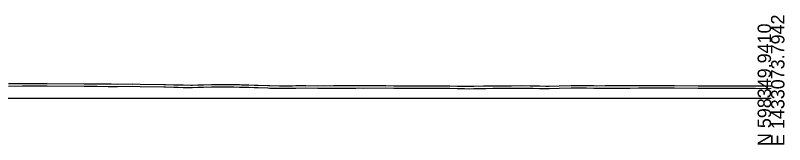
# Model space of a CAD drawing. Extents: x -26 to 2203, y -10 to 12201.
# Drawn here: x 442.1 to 602.8, y 1990.3 to 2017.3 of the extents above; entities that cross this region are included whole.
import ezdxf

# ---------------------------------------------------------------- set-up
doc = ezdxf.new("R2010")
doc.units = 0
for name, color, linetype in [('DESIGN - SHEET - Light Grid', 7, 'Continuous'), ('SURVEY - GROUND - Bottom of Topsoil Layer', 7, 'Continuous'), ('SURVEY - GROUND - Top of Ground', 7, 'Continuous')]:
    doc.layers.add(name, color=color, linetype=linetype)

msp = doc.modelspace()

# ---------------------------------------------------------------- linework, layer by layer
at = {"layer": 'DESIGN - SHEET - Light Grid'}
msp.add_line((300, 2000), (600, 2000), dxfattribs=at)
at = {"layer": 'SURVEY - GROUND - Bottom of Topsoil Layer'}
for p, q in [((440.59, 2002.54), (443.51, 2002.59)), ((443.51, 2002.59), (444.6, 2002.55)), ((444.6, 2002.55), (448.7, 2002.59)), ((448.7, 2002.59), (456.41, 2002.5)), ((456.41, 2002.5), (457.53, 2002.5)), ((457.53, 2002.5), (459.12, 2002.48)), ((459.12, 2002.48), (461.46, 2002.47)), ((461.46, 2002.47), (462.04, 2002.47)), ((462.04, 2002.47), (463.42, 2002.45)), ((463.42, 2002.45), (466.53, 2002.48)), ((466.53, 2002.48), (468.13, 2002.46)), ((468.13, 2002.46), (473.1, 2002.38)), ((473.1, 2002.38), (473.43, 2002.37)), ((473.43, 2002.37), (475.18, 2002.3)), ((475.18, 2002.3), (476.08, 2002.28)), ((476.08, 2002.28), (477.14, 2002.26)), ((477.14, 2002.26), (478.73, 2002.25)), ((478.73, 2002.25), (479.1, 2002.25)), ((479.1, 2002.25), (480.16, 2002.27)), ((480.16, 2002.27), (481.06, 2002.29)), ((481.06, 2002.29), (481.38, 2002.3)), ((481.38, 2002.3), (483.02, 2002.36)), ((483.02, 2002.36), (484.03, 2002.36)), ((484.03, 2002.36), (484.98, 2002.39)), ((484.98, 2002.39), (486.94, 2002.37)), ((486.94, 2002.37), (487.69, 2002.35)), ((487.69, 2002.35), (488.9, 2002.33)), ((488.9, 2002.33), (489.33, 2002.31)), ((489.33, 2002.31), (490.86, 2002.27)), ((490.86, 2002.27), (491.98, 2002.23)), ((491.98, 2002.23), (492.83, 2002.21)), ((492.83, 2002.21), (494.79, 2002.15)), ((494.79, 2002.15), (495.21, 2002.13)), ((495.21, 2002.13), (497.29, 2002.08)), ((497.29, 2002.08), (498.71, 2002.09)), ((498.71, 2002.09), (499.94, 2002.1)), ((499.94, 2002.1), (500.67, 2002.12)), ((500.67, 2002.12), (502.74, 2002.14)), ((502.74, 2002.14), (505.24, 2002.11)), ((505.24, 2002.11), (506.55, 2002.12)), ((506.55, 2002.12), (507.89, 2002.11)), ((507.89, 2002.11), (508.51, 2002.12)), ((508.51, 2002.12), (510.54, 2002.13)), ((510.54, 2002.13), (512.43, 2002.12)), ((512.43, 2002.12), (513.19, 2002.12)), ((513.19, 2002.12), (513.82, 2002.14)), ((513.82, 2002.14), (514.78, 2002.13)), ((514.78, 2002.13), (519.51, 2002.14)), ((519.51, 2002.14), (521.14, 2002.1)), ((521.14, 2002.1), (523.47, 2002.09)), ((523.47, 2002.09), (524.19, 2002.09)), ((524.19, 2002.09), (525.32, 2002.09)), ((525.32, 2002.09), (526.44, 2002.09)), ((526.44, 2002.09), (528.11, 2002.1)), ((528.11, 2002.1), (529.09, 2002.09)), ((529.09, 2002.09), (530.07, 2002.08)), ((530.07, 2002.08), (532.03, 2002.08)), ((532.03, 2002.08), (532.84, 2002.07)), ((532.84, 2002.07), (534.4, 2002.03)), ((534.4, 2002.03), (535.95, 2002)), ((535.95, 2002), (537.05, 2001.99)), ((537.05, 2001.99), (537.91, 2002)), ((537.91, 2002), (539.87, 2002.05)), ((539.87, 2002.05), (540.37, 2002.06)), ((540.37, 2002.06), (541.83, 2002.1)), ((541.83, 2002.1), (542.35, 2002.1)), ((542.35, 2002.1), (543.79, 2002.09)), ((543.79, 2002.09), (545, 2002.1)), ((545, 2002.1), (545.75, 2002.11)), ((545.75, 2002.11), (547.9, 2002.13)), ((547.9, 2002.13), (549.67, 2002.11)), ((549.67, 2002.11), (550.3, 2002.1)), ((550.3, 2002.1), (551.63, 2002.05)), ((551.63, 2002.05), (552.95, 2002.03)), ((552.95, 2002.03), (553.59, 2002.04)), ((553.59, 2002.04), (555.7, 2002.07)), ((555.7, 2002.07), (558.25, 2002.15)), ((558.25, 2002.15), (559.79, 2002.16)), ((559.79, 2002.16), (560.9, 2002.17)), ((560.9, 2002.17), (561.44, 2002.17)), ((561.44, 2002.17), (562.95, 2002.12)), ((562.95, 2002.12), (563.55, 2002.11)), ((563.55, 2002.11), (565.36, 2002.13)), ((565.36, 2002.13), (566.2, 2002.13)), ((566.2, 2002.13), (570.48, 2002.13)), ((570.48, 2002.13), (572.27, 2002.14)), ((572.27, 2002.14), (573.2, 2002.17)), ((573.2, 2002.17), (573.6, 2002.17)), ((573.6, 2002.17), (574.16, 2002.16)), ((574.16, 2002.16), (574.94, 2002.17)), ((574.94, 2002.17), (579.82, 2002.17)), ((579.82, 2002.17), (584.76, 2002.11)), ((584.76, 2002.11), (588.88, 2002.08)), ((588.88, 2002.08), (595.36, 2002.1)), ((595.36, 2002.1), (596.72, 2002.08)), ((596.72, 2002.08), (597.52, 2002.06)), ((597.52, 2002.06), (600, 2002.08))]:
    msp.add_line(p, q, dxfattribs=at)
at = {"layer": 'SURVEY - GROUND - Top of Ground'}
for p, q in [((440.59, 2003.04), (443.51, 2003.09)), ((443.51, 2003.09), (444.6, 2003.05)), ((444.6, 2003.05), (448.7, 2003.09)), ((448.7, 2003.09), (456.41, 2003)), ((456.41, 2003), (457.53, 2003)), ((457.53, 2003), (459.12, 2002.98)), ((459.12, 2002.98), (461.46, 2002.97)), ((461.46, 2002.97), (462.04, 2002.97)), ((462.04, 2002.97), (463.42, 2002.95)), ((463.42, 2002.95), (466.53, 2002.98)), ((466.53, 2002.98), (468.13, 2002.96)), ((468.13, 2002.96), (473.1, 2002.88)), ((473.1, 2002.88), (473.43, 2002.87)), ((473.43, 2002.87), (475.18, 2002.8)), ((475.18, 2002.8), (476.08, 2002.78)), ((476.08, 2002.78), (477.14, 2002.76)), ((477.14, 2002.76), (478.73, 2002.75)), ((478.73, 2002.75), (479.1, 2002.75)), ((479.1, 2002.75), (480.16, 2002.77)), ((480.16, 2002.77), (481.06, 2002.79)), ((481.06, 2002.79), (481.38, 2002.8)), ((481.38, 2002.8), (483.02, 2002.86)), ((483.02, 2002.86), (484.03, 2002.86)), ((484.03, 2002.86), (484.98, 2002.89)), ((484.98, 2002.89), (486.94, 2002.87)), ((486.94, 2002.87), (487.69, 2002.85)), ((487.69, 2002.85), (488.9, 2002.83)), ((488.9, 2002.83), (489.33, 2002.81)), ((489.33, 2002.81), (490.86, 2002.77)), ((490.86, 2002.77), (491.98, 2002.73)), ((491.98, 2002.73), (492.83, 2002.71)), ((492.83, 2002.71), (494.79, 2002.65)), ((494.79, 2002.65), (495.21, 2002.63)), ((495.21, 2002.63), (497.29, 2002.58)), ((497.29, 2002.58), (498.71, 2002.59)), ((498.71, 2002.59), (499.94, 2002.6)), ((499.94, 2002.6), (500.67, 2002.62)), ((500.67, 2002.62), (502.74, 2002.64)), ((502.74, 2002.64), (505.24, 2002.61)), ((505.24, 2002.61), (506.55, 2002.62)), ((506.55, 2002.62), (507.89, 2002.61)), ((507.89, 2002.61), (508.51, 2002.62)), ((508.51, 2002.62), (510.54, 2002.63)), ((510.54, 2002.63), (512.43, 2002.62)), ((512.43, 2002.62), (513.19, 2002.62)), ((513.19, 2002.62), (513.82, 2002.64)), ((513.82, 2002.64), (514.78, 2002.63)), ((514.78, 2002.63), (519.51, 2002.64)), ((519.51, 2002.64), (521.14, 2002.6)), ((521.14, 2002.6), (523.47, 2002.59)), ((523.47, 2002.59), (524.19, 2002.59)), ((524.19, 2002.59), (525.32, 2002.59)), ((525.32, 2002.59), (526.44, 2002.59)), ((526.44, 2002.59), (528.11, 2002.6)), ((528.11, 2002.6), (529.09, 2002.59)), ((529.09, 2002.59), (530.07, 2002.58)), ((530.07, 2002.58), (532.03, 2002.58)), ((532.03, 2002.58), (532.84, 2002.57)), ((532.84, 2002.57), (534.4, 2002.53)), ((534.4, 2002.53), (535.95, 2002.5)), ((535.95, 2002.5), (537.05, 2002.49)), ((537.05, 2002.49), (537.91, 2002.5)), ((537.91, 2002.5), (539.87, 2002.55)), ((539.87, 2002.55), (540.37, 2002.56)), ((540.37, 2002.56), (541.83, 2002.6)), ((541.83, 2002.6), (542.35, 2002.6)), ((542.35, 2002.6), (543.79, 2002.59)), ((543.79, 2002.59), (545, 2002.6)), ((545, 2002.6), (545.75, 2002.61)), ((545.75, 2002.61), (547.9, 2002.63)), ((547.9, 2002.63), (549.67, 2002.61)), ((549.67, 2002.61), (550.3, 2002.6)), ((550.3, 2002.6), (551.63, 2002.55)), ((551.63, 2002.55), (552.95, 2002.53)), ((552.95, 2002.53), (553.59, 2002.54)), ((553.59, 2002.54), (555.7, 2002.57)), ((555.7, 2002.57), (558.25, 2002.65)), ((558.25, 2002.65), (559.79, 2002.66)), ((559.79, 2002.66), (560.9, 2002.67)), ((560.9, 2002.67), (561.44, 2002.67)), ((561.44, 2002.67), (562.95, 2002.62)), ((562.95, 2002.62), (563.55, 2002.61)), ((563.55, 2002.61), (565.36, 2002.63)), ((565.36, 2002.63), (566.2, 2002.63)), ((566.2, 2002.63), (570.48, 2002.63)), ((570.48, 2002.63), (572.27, 2002.64)), ((572.27, 2002.64), (573.2, 2002.67)), ((573.2, 2002.67), (573.6, 2002.67)), ((573.6, 2002.67), (574.16, 2002.66)), ((574.16, 2002.66), (574.94, 2002.67)), ((574.94, 2002.67), (579.82, 2002.67)), ((579.82, 2002.67), (584.76, 2002.61)), ((584.76, 2002.61), (588.88, 2002.58)), ((588.88, 2002.58), (595.36, 2002.6)), ((595.36, 2002.6), (596.72, 2002.58)), ((596.72, 2002.58), (597.52, 2002.56)), ((597.52, 2002.56), (600, 2002.58))]:
    msp.add_line(p, q, dxfattribs=at)

# ---------------------------------------------------------------- texts
at = {"layer": 'DESIGN - SHEET - Light Grid'}
for s, p in [('E 1433073.7942', (602.8, 1990)), ('N 598349.9410', (600, 1990))]:
    msp.add_text(s, height=2.8, rotation=90, dxfattribs=at).set_placement(p)

doc.saveas('drawing.dxf')
